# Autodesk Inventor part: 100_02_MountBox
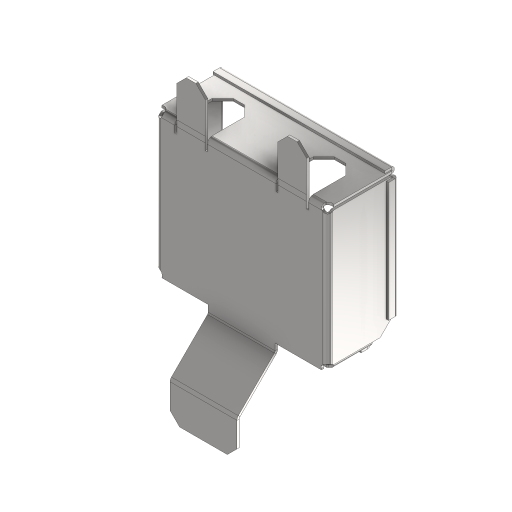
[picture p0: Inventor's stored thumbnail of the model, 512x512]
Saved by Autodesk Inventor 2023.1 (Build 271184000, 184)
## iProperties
Company: Fabian Stasiak CAD Consulting
Category: Autodesk® Inventor® Tutorial Series
Created: 2005-11
Part Number: 100_02_MountBox
Material: Steel
Document SubType Name: Sheet Metal
Designer: F.Stasiak
Density: 1 g/cm^3
Sheet Metal Rule: Steel 2.5 mm/Round
Sheet Metal Width: 328,562 mm
Sheet Metal Length: 332,240 mm
Sheet Metal Area: 109161,518 mm^2
Appearance: Semi-Polished
Description: Mounting Box RX7
Catalog Web Link: www.expertbooks.eu
Flat Pattern Width: 32.8562 cm
Flat Pattern Length: 33.224 cm
Flat Pattern Area: 1091.62 cm^2
FLATAREA: =<FLAT PATTERN AREA>
Thickness: 2,500 mm
Author: F.Stasiak
Subject: Sheet Metal Design. Basic and Advanced techniques
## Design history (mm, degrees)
node "Powierzchnia1"
  sketch "Szkic2"
    geometry: L1 (-75, 90)-(75, 90); L2 (75, 90)-(75, -90); L3 (75, -90)-(-75, -90); L4 (-75, -90)-(-75, 90); L5 (0, 90)-(0, -90); 2 further points
    constraints: 10 end point, 3 midpoint, 2 parallel, 1 coincident, 1 horizontal, 1 perpendicular
    dimensions: "d2" = 150 distance of L2.end L3.end; "d3" = 180 distance of L1.end L2.end
node "Kołnierz6"
feature "Fazowanie narożnika3" dims "d68" = 20, "d69" = 6, angle "d70" = 45 deg
node "Kołnierz7"
feature "Narożnik4" dims "d156" = 10 (= CornerReliefSize), "d157" = 2.5 (= BendRadius), "d158" = 2.5 (= GapSize), "d159" = 0, "d160" = 10, "d223" = 2.5 (= Thickness)
feature "Narożnik5" dims "d161" = 10 (= CornerReliefSize), "d162" = 2.5 (= BendRadius), "d163" = 2.5 (= GapSize), "d164" = 0, "d165" = 10, "d223" = 2.5 (= Thickness)
node "Płaszczyzna konstrukcyjna2"
node "Powierzchnia3"
  sketch "Szkic11"
    geometry: L1 (-231, 119.076)-(-195, 119.076); L2 (-195, 119.076)-(-195, 49.076); L3 (-195, 49.076)-(-231, 49.076); L4 (-231, 49.076)-(-231, 119.076); L5 (-142.5, 44.076)-(-145, 44.076) reference; L6 (-142.5, 124.076)-(-145, 124.076) reference; L7 (-145, 167.518)-(-145, 0.634) reference; 3 further points
    constraints: 8 end point, 2 parallel, 1 horizontal, 1 perpendicular
    dimensions: "d82" = 5 distance between parallel lines of L5 L3; "d83" = 5 distance between parallel lines of L6 L1 (= d82); "d84" = 36 distance of L1.start L1.end; "d85" = 50 distance between parallel lines of L7 L2
feature "Fazowanie narożnika4" dims "d91" = 10, "d92" = 6, angle "d93" = 45 deg
feature "Bend13" [Gięcie] dims "d223" = 2.5 (= Thickness), "d224" = 2.5 (= BendReliefWidth), "d225" = 1.25 (= BendReliefDepth), "d226" = 5 (= MinimumRemnant), "d227" = 2.5 (= TransitionRadius), "d228" = 2.5 (= BendRadius), "SeamGap" = 0.01
node "Unfold1"
sketch "Sketch26"
  geometry: L1 (132.163, 155)-(190.163, 155); L2 (190.163, 155)-(190.163, 121); L3 (190.163, 121)-(132.163, 121); L4 (132.163, 121)-(132.163, 155); L5 (0, 175)-(138.153, 175) reference; L6 (210.163, 175)-(210.163, -5) reference; L7 (132.163, 153)-(188.163, 153); L8 (188.163, 153)-(188.163, 123); L9 (188.163, 123)-(132.163, 123); 3 further points
  constraints: 14 end point, 3 perpendicular, 2 horizontal, 2 midpoint, 2 parallel, 2 point on line, 1 horizontal alignment
  dimensions: "d229" = 58 distance of L2.end L3.end; "d230" = 34 distance of L1.end L2.end; "d231" = 20 distance between parallel lines of L1 L5; "d232" = 20 distance between parallel lines of L6 L2; "d233" = 30 distance between parallel lines of L9 L7; "d234" = 56 distance of L7.start L7.end
cut "Cut3" sketch "Sketch26" dims "d235" = 2.5 (= Thickness), "d236" = 0
feature "Corner Chamfer9" [Fazowanie narożnika] dims "d237" = 10, "d238" = 6, angle "d239" = 45 deg
feature "Corner Chamfer10" [Fazowanie narożnika] dims "d240" = 11, "d241" = 6, angle "d242" = 45 deg
mirror "Mirror3"
node "Refold1"
feature "Hem11" dims "d223" = 2.5 (= Thickness), "d243" = 2.5 (= BendReliefWidth), "d244" = 1.25 (= BendReliefDepth), "d245" = 5 (= MinimumRemnant), "d246" = 2.5 (= TransitionRadius), "d247" = 10 (= 4 x Thickness), "d248" = 1.25 (= 0.5 x Thickness), "d249" = 0.625 (= 0.5 x d248), "SeamGap" = 0.01
feature "Hem12" dims "d223" = 2.5 (= Thickness), "d250" = 2.5 (= BendReliefWidth), "d251" = 1.25 (= BendReliefDepth), "d252" = 5 (= MinimumRemnant), "d253" = 2.5 (= TransitionRadius), "d254" = 10 (= 4 x Thickness), "d255" = 1.25 (= 0.5 x Thickness), "d256" = 0.625 (= 0.5 x d255), "SeamGap" = 0.01
feature "Hem13" dims "d223" = 2.5 (= Thickness), "d257" = 2.5 (= BendReliefWidth), "d258" = 1.25 (= BendReliefDepth), "d259" = 5 (= MinimumRemnant), "d260" = 2.5 (= TransitionRadius), "d261" = 10 (= 4 x Thickness), "d262" = 1.25 (= 0.5 x Thickness), "d263" = 0.625 (= 0.5 x d262), "SeamGap" = 0.01
feature "Hem14" dims "d223" = 2.5 (= Thickness), "d264" = 2.5 (= BendReliefWidth), "d265" = 1.25 (= BendReliefDepth), "d266" = 5 (= MinimumRemnant), "d267" = 2.5 (= TransitionRadius), "d268" = 10 (= 4 x Thickness), "d269" = 1.25 (= 0.5 x Thickness), "d270" = 0.625 (= 0.5 x d269), "SeamGap" = 0.01
feature "Hem15" dims "d223" = 2.5 (= Thickness), "d271" = 2.5 (= BendReliefWidth), "d272" = 1.25 (= BendReliefDepth), "d273" = 5 (= MinimumRemnant), "d274" = 2.5 (= TransitionRadius), "d275" = 10 (= 4 x Thickness), "d276" = 1.25 (= 0.5 x Thickness), "d277" = 0.625 (= 0.5 x d276), "SeamGap" = 0.01
node "Bryła1"
node "Korpusy bryłowe"
node "Korpusy powierzchniowe"
feature "Płyta1" dims "d223" = 2.5 (= Thickness)
sketch "Szkic9"
  geometry: L1 (0, 70)-(-150, 70); L2 (-150, 70)-(-150, 0); 1 other entity
  constraints: 4 end point, 4 other
feature "Płyta8" dims "d56" = 2.5 (= BendReliefWidth), "d57" = 1.25 (= BendReliefDepth), "d58" = 5 (= MinimumRemnant), "d59" = 2.5 (= BendRadius), "d60" = 70 (= WW), "d61" = 90 deg, "d62" = 2.5 (= BendRadius), "d63" = 10 (= CornerReliefSize), "d64" = 2.5 (= GapSize), "d65" = 2.5 (= JacobiRadiusSize), "d66" = 10, "d67" = 10, "d223" = 2.5 (= Thickness), "SeamGap" = 0.01
feature "Gięcie7" dims "d56" = 2.5 (= BendReliefWidth), "d57" = 1.25 (= BendReliefDepth), "d58" = 5 (= MinimumRemnant), "d59" = 2.5 (= BendRadius), "d60" = 70 (= WW), "d61" = 90 deg, "d62" = 2.5 (= BendRadius), "d223" = 2.5 (= Thickness), "SeamGap" = 0.01
feature "Narożnik1" dims "d60" = 70 (= WW), "d61" = 90 deg, "d63" = 10 (= CornerReliefSize), "d64" = 2.5 (= GapSize), "d65" = 2.5 (= JacobiRadiusSize)
sketch "Szkic10"
  geometry: L1 (50, 0)-(50, 45); L2 (50, 45)-(0, 45); 1 other entity
  constraints: 4 end point, 4 other
feature "Płyta9" dims "d71" = 2.5 (= BendReliefWidth), "d72" = 1.25 (= BendReliefDepth), "d73" = 5 (= MinimumRemnant), "d74" = 2.5 (= BendRadius), "d75" = 50, "d76" = 90 deg, "d77" = 2.5 (= BendRadius), "d78" = 10 (= CornerReliefSize), "d79" = 2.5 (= GapSize), "d80" = 2.5 (= JacobiRadiusSize), "d223" = 2.5 (= Thickness), "SeamGap" = 0.01
feature "Gięcie8" dims "d71" = 2.5 (= BendReliefWidth), "d72" = 1.25 (= BendReliefDepth), "d73" = 5 (= MinimumRemnant), "d74" = 2.5 (= BendRadius), "d75" = 50, "d76" = 90 deg, "d77" = 2.5 (= BendRadius), "d223" = 2.5 (= Thickness), "SeamGap" = 0.01
feature "Narożnik2" dims "d75" = 50, "d76" = 90 deg, "d78" = 10 (= CornerReliefSize), "d79" = 2.5 (= GapSize), "d80" = 2.5 (= JacobiRadiusSize)
feature "Płyta10" dims "d86" = 2.5 (= BendRadius), "d87" = 2.5 (= BendReliefWidth), "d89" = 5 (= MinimumRemnant), "d223" = 2.5 (= Thickness)
feature "Gięcie9" dims "d86" = 2.5 (= BendRadius), "d87" = 2.5 (= BendReliefWidth), "d88" = 1.25 (= BendReliefDepth), "d89" = 5 (= MinimumRemnant), "d90" = 2.5 (= BendRadius), "d223" = 2.5 (= Thickness), "SeamGap" = 0.01
sketch "Sketch27"
  geometry: L1 (2.5, 0)-(0, 0); L2 (-1.25, 0)-(-1.25, -6.875); L3 (-1.25, -6.875)-(-3.75, -6.875); L4 (-3.75, -6.875)-(-3.75, 0); A1 r 0.625 centre (-0.625, 0) between (0, 0) and (-1.25, 0); A2 r 3.125 centre (-0.625, 0) between (2.5, 0) and (-3.75, 0)
  constraints: 8 end point, 4 point on circle
sketch "Sketch28"
  geometry: L1 (2.5, 0)-(0, 0); L2 (-1.25, 0)-(-1.25, -6.875); L3 (-1.25, -6.875)-(-3.75, -6.875); L4 (-3.75, -6.875)-(-3.75, 0); A1 r 0.625 centre (-0.625, 0) between (0, 0) and (-1.25, 0); A2 r 3.125 centre (-0.625, 0) between (2.5, 0) and (-3.75, 0)
  constraints: 8 end point, 4 point on circle
sketch "Sketch29"
  geometry: L1 (2.5, 0)-(0, 0); L2 (-1.25, 0)-(-1.25, -6.875); L3 (-1.25, -6.875)-(-3.75, -6.875); L4 (-3.75, -6.875)-(-3.75, 0); A1 r 0.625 centre (-0.625, 0) between (0, 0) and (-1.25, 0); A2 r 3.125 centre (-0.625, 0) between (2.5, 0) and (-3.75, 0)
  constraints: 8 end point, 4 point on circle
sketch "Sketch30"
  geometry: L1 (2.5, 0)-(0, 0); L2 (-1.25, 0)-(-1.25, -6.875); L3 (-1.25, -6.875)-(-3.75, -6.875); L4 (-3.75, -6.875)-(-3.75, 0); A1 r 0.625 centre (-0.625, 0) between (0, 0) and (-1.25, 0); A2 r 3.125 centre (-0.625, 0) between (2.5, 0) and (-3.75, 0)
  constraints: 8 end point, 4 point on circle
sketch "Sketch31"
  geometry: L1 (2.5, 0)-(0, 0); L2 (-1.25, 0)-(-1.25, -6.875); L3 (-1.25, -6.875)-(-3.75, -6.875); L4 (-3.75, -6.875)-(-3.75, 0); A1 r 0.625 centre (-0.625, 0) between (0, 0) and (-1.25, 0); A2 r 3.125 centre (-0.625, 0) between (2.5, 0) and (-3.75, 0)
  constraints: 8 end point, 4 point on circle
feature "Definition1"
other parameters: "Thickness" = 2.5 (derived), "BendRadius" = 2.5 (= Thickness), "BendReliefWidth" = 2.5 (= Thickness), "BendReliefDepth" = 1.25 (= 0.5 x Thickness), "MinimumRemnant" = 5 (= 2 x Thickness), "TransitionRadius" = 2.5 (= BendRadius), "d4" = 2.5 (= BendRadius), "JacobiRadiusSize" = 2.5 (= BendRadius), "GapSize" = 2.5 (= Thickness), "Thickness" = 2.5, "BendReliefDepth" = 1.25, "MinimumRemnant" = 5, "BendRadius" = 2.5, "TransitionRadius" = 2.5, "JacobiRadiusSize" = 2.5, "BendReliefWidth" = 2.5, "GapSize" = 2.5
